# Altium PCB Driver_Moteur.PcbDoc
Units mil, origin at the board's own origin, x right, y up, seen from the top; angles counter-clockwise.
Board outline 3370 x 2000 mil, 2 copper layers (Top Layer, Bottom Layer); 25 components, 15 nets, 72 pads, 0 vias.
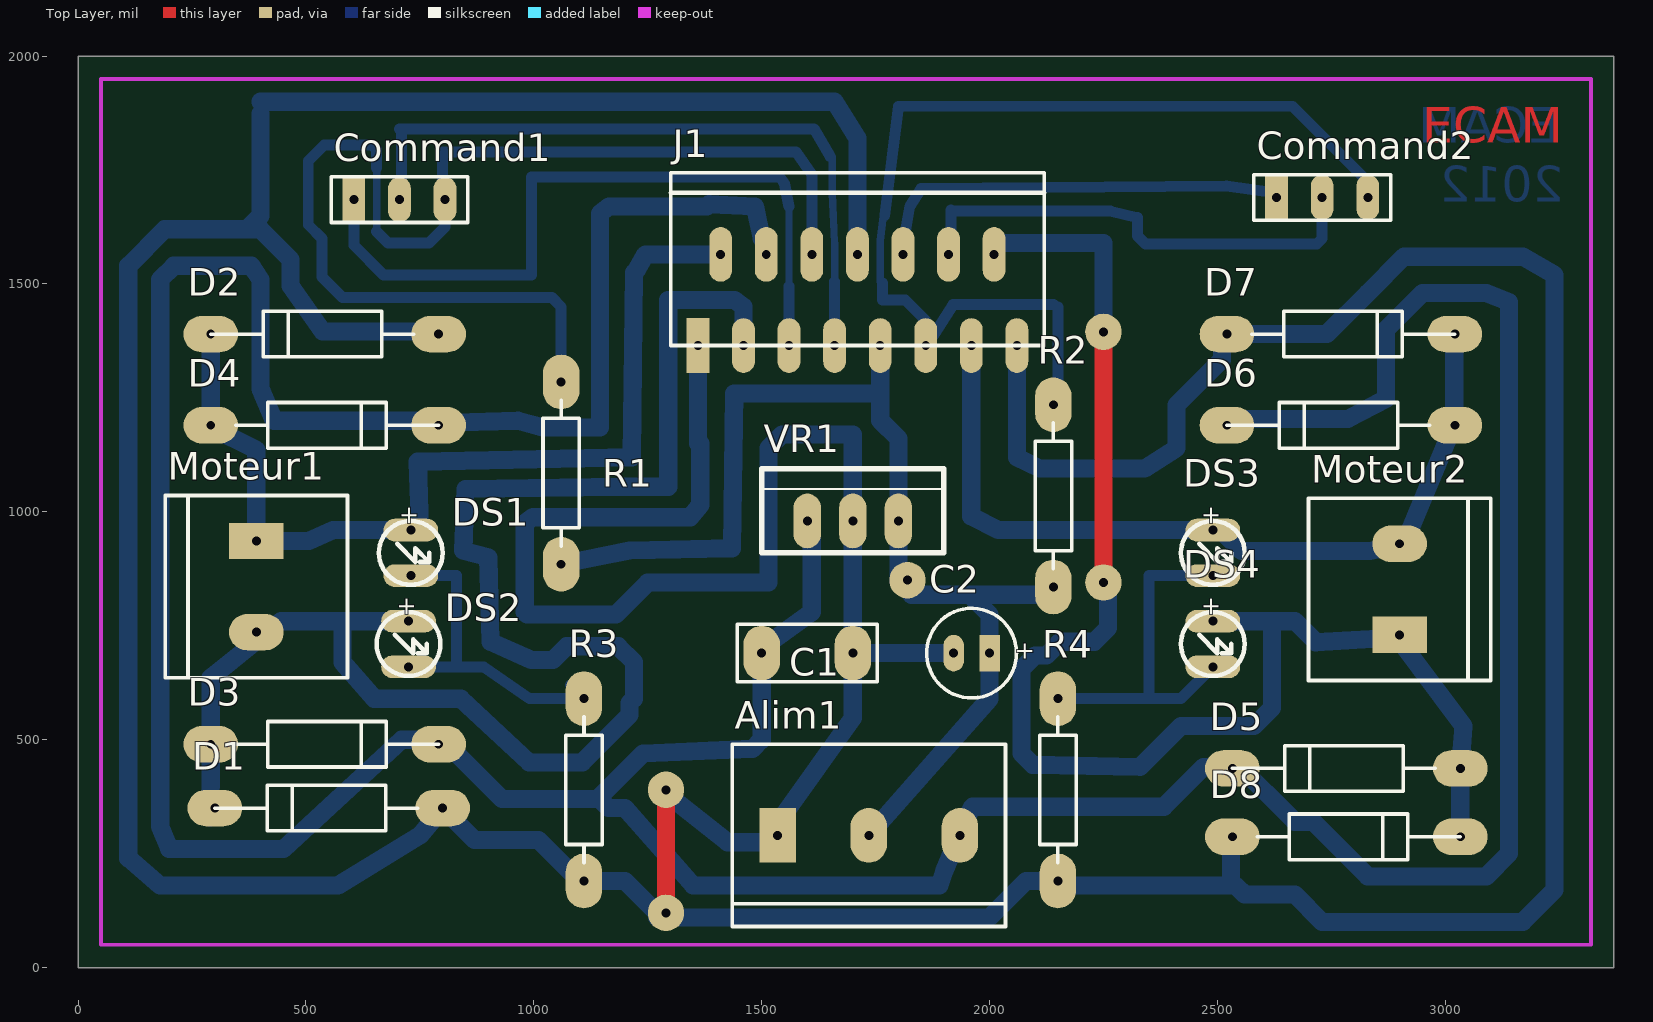
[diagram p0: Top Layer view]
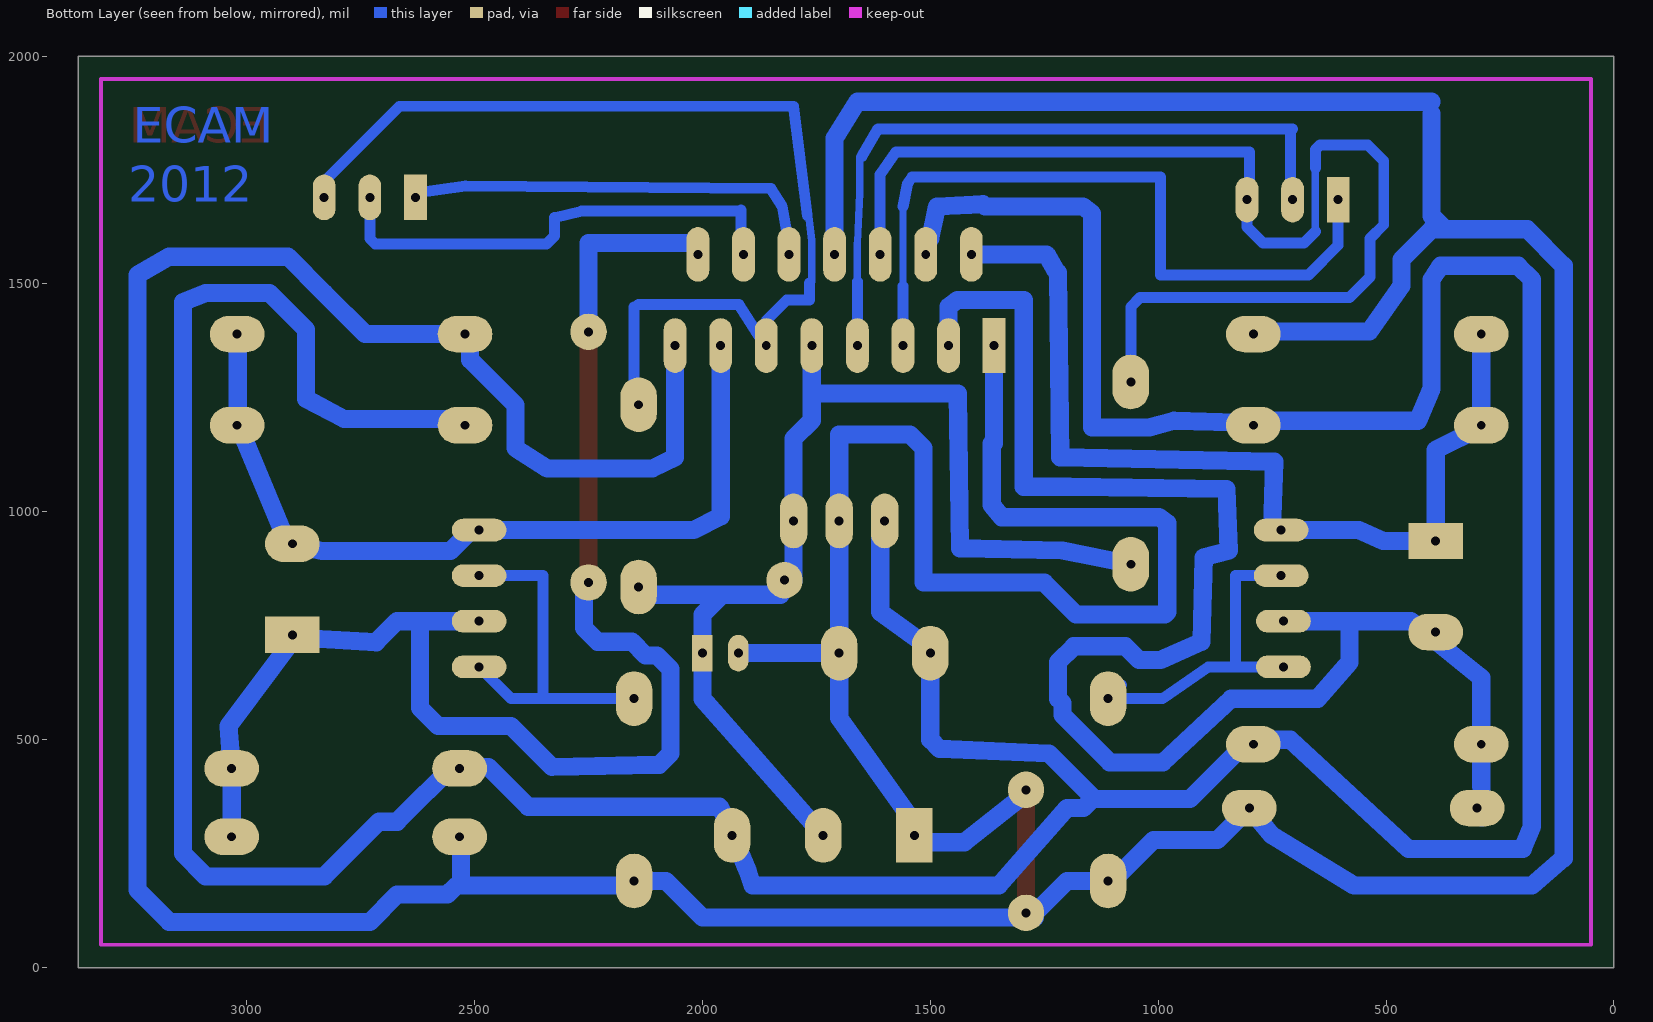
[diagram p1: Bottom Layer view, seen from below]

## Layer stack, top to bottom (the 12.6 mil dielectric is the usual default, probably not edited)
Top Layer: signal copper 1.4
Dielectric: core 12.6, FR-4, Dk 4.8
Bottom Layer: signal copper 1.4

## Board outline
0,0 3370,0 3370,2000 0,2000

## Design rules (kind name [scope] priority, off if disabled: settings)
Clearance "Clearance P DIP" [(IsTrack) vs (IsPad AND(
HasFootprint('DIP*')))] p1: gap=12
Clearance "Clearance PT" [(isTrack) vs (isPad)] p2: gap=16
Clearance "Clearance TT" [(isTrack) vs (isTrack)] p3: gap=24
Clearance "Clearance PP" [(IsPad) vs (IsPad)] p4: gap=24
Clearance [All] p5: gap=40
ComponentClearance [All] p1: gap=10 collisioncheckmode=0
HoleSize [All] p1: absolutevalues=TRUE maxlimit=21.65 minlimit=17.72 maxpercent=80.000 minpercent=20.000
PolygonConnect [All] p1: connectstyle=Relief reliefconductorwidth=10 reliefentries=4 polygonreliefangle="90 Angle"
RoutingCorners [All] p1: cornerstyle=45-Degree minsetback=100 maxsetback=1000
RoutingLayers [All] p1: top layer_v5=FALSE bottom layer_v5=TRUE
RoutingVias "ECAM Vias" [All] p1: holewidth=19.68 width=80 viastyle="Through Hole" minholewidth=17.72 minwidth=60 maxholewidth=21.65 maxwidth=120
SolderMaskExpansion [All] p1: expansion=4
TestPointUsage [All] p1: valid=0 allowmultiple=FALSE
Testpoint [All] p1: side=15 testpointundercomponent=TRUE minsize=40 maxsize=100 preferedsize=60 minholesize=0 maxholesize=40 preferedholesize=32 testpointgrid=1 style=1023 order=0-112345678
Width Width_GND [InNet('GND')] p1: maxlimit=1000 minlimit=24 preferedwidth=40
Width Width_VCC [InNet('VCC')] p2: maxlimit=1000 minlimit=24 preferedwidth=40
Width [All] p3: maxlimit=1000 minlimit=16 preferedwidth=24 bottomlayer_prefwidth=16 minimp=50.000000 maximp=50.000000 favimp=50.000000
14 further rules are at their usual default settings.

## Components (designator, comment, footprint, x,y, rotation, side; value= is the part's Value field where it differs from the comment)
Alim1 "Connecteur 3" CONVIS-3 1535,290 r0 top
C1 "Condensateur" CAPR5.08-7.8x3.2 1500,690 r0 top
C2 "Cond pol radial" CAPPR2-5x6.8 2000,690 r180 top
Command1 "Connecteur 3" HDR1X3 605,1685 r0 top
Command2 "Connecteur 3" HDR1X3 2630,1690 r0 top
D1 "Diode Schottky" DIODE-0.4 800,350 r180 top
D2 "Diode Schottky" DIODE-0.4 791,1390 r180 top
D3 "Diode Schottky" DIODE-0.4 291,490 r0 top
D4 "Diode Schottky" DIODE-0.4 291,1190 r0 top
D5 "Diode Schottky" DIODE-0.4 3033,437 r180 top
D6 "Diode Schottky" DIODE-0.4 3021,1190 r180 top
D7 "Diode Schottky" DIODE-0.4 2521,1390 r0 top
D8 "Diode Schottky" DIODE-0.4 2533,287 r0 top
DS1 "LED" "Led 0.1" 730,960 r270 top
DS2 "LED" "Led 0.1" 725,760 r270 top
DS3 "LED" "Led 0.1" 2490,960 r270 top
DS4 "LED" "Led 0.1" 2490,760 r270 top
J1 "L298" MultiWatt15 1200,1365 r0 top
Moteur1 "Connecteur 2" CONVIS-2 391,936 r270 top
Moteur2 "Connecteur 2" CONVIS-2 2900,730 r90 top
R1 "Résistance" AXIAL-0.4 1060,885 r90 top
R2 "Résistance" AXIAL-0.4 2140,1235 r270 top
R3 "Résistance" AXIAL-0.4 1110,190 r90 top
R4 "Résistance" AXIAL-0.4 2150,190 r90 top
VR1 "7805" "TO-220 V" 1600,980 r0 top

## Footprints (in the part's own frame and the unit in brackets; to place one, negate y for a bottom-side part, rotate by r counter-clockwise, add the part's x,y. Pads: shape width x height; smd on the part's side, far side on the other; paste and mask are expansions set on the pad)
AXIAL-0.4 [mil] "Resistor; 2 Leads"
  oval 120x80 hole 19.68 paste+0 mask+0: 1(0,0) 2(400,0)
  silkscreen extent 40,-40 360,40
CAPPR2-5x6.8 [mil] "Capacitor, Electrolytic, Radial; Body 5 x 6.8 mm (Dia.xH typ); Pin Spacing 2 mm (typ)"
  rect 45x80 hole 19.68 paste+0 mask+0: 1(0,0)
  oval 45x80 hole 19.68 paste+0 mask+0: 2(78.74,0)
  silkscreen extent -59,-98 138,98
CAPR5.08-7.8x3.2 [mil] "Capacitor, Ceramic, Thru-Hole, Dipped Radial; Body 7.8 x 3.2 mm (WxT) Pin Spacing 5.08 mm (typ)"
  oval 80x120 hole 19.68 paste+0 mask+0: 1(0,0) 2(200,0)
  silkscreen extent -54,-63 254,63
CONVIS-2 [mil] "Connecteur à vis 2 contacts Pitch 5.08"
  rect 80x120 hole 19.68 paste+0 mask+0: 1(0,0)
  oval 80x120 hole 19.68 paste+0 mask+0: 2(200,0)
  silkscreen extent -100,-200 300,200
CONVIS-3 [mil] "Connecteur à vis 3 contacts Pitch 5.08"
  rect 80x120 hole 19.68 paste+0 mask+0: 1(0,0)
  oval 80x120 hole 19.68 paste+0 mask+0: 2(200,0) 3(400,0)
  silkscreen extent -100,-200 500,200
DIODE-0.4 [mil] "Tunnel Diode - Dependent Source Model; 2 Leads"
  oval 120x80 hole 19.68 paste+0 mask+0: 1(0,0) 2(500,0)
  silkscreen extent 55,-50 500,50
HDR1X3 [mm] "Connector; Header; 3 Position"
  rect 1.27x2.54 hole 0.5 paste+0 mask+0: 1(0,0)
  oval 1.27x2.54 hole 0.5 paste+0 mask+0: 2(2.54,0) 3(5.08,0)
  silkscreen extent -1.27,-1.27 6.35,1.27
"Led 0.1" [mil] "Led Verticale"
  oval 50x120 hole 19.68 paste+0 mask+0: 1(0,0) 2(100,0)
  silkscreen extent -20,-70 120,70
MultiWatt15 [mil] "MultiWatt15; 15 Leads; Row Spacing 5.08 mm; Pitch 2.54 mm"
  rect 50x120 hole 19.68 paste+0 mask+0: CSA(160,0)
  oval 50x120 hole 19.68 paste+0 mask+0: CSB(860,0) ENA(410,200) ENB(660,0) GND(510,200) input1(360,0) input2(460,0) input3(610,200) input4(710,200) OUT1(210,200) OUT2(260,0) OUT3(760,0) OUT4(810,200) VS(310,200) VSS(560,0)
  silkscreen extent 100,0 920,379
"TO-220 V" [mil] "TO-220 Vertical"
  oval 60x120 hole 19.68 paste+0 mask+0: 1(0,0) 2(100,0) 3(200,0)
  silkscreen extent -100,-70 300,115

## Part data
Alim1 Command1 Command2 J1 Moteur1 Moteur2: "Connecteur"
C2: "Condensateur polatisé"
R1 R2 R3 R4: "Résistance standard"
VR1: "Régulateur 5V"

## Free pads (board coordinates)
  round 80 hole 19.68: 0(2250,845) 1(1290,390) 1(1820,850) 1(2250,1395) 2(1290,120)

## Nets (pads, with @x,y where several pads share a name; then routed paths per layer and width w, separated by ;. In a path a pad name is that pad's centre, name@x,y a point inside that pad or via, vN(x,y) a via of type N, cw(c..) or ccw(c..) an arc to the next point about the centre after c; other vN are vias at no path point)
+5: Alim1.2 C2.1 J1.VSS pad.1@1820,850 R1.1 R2.2 VR1.3 | length 2602.8
  Bottom Layer w24: 1590,1260 1600,1260 ; pad.1@1800,847 pad.1@1829,818 ; R2.2@2133,818 R2.2@2150,835
  Bottom Layer w40: R1.1 1210,915 1435,920 1440,1260 1595,1260 1590,1260 ; 1600,1260 1740,1260 ; Alim1.2 2000,590 2000,775 1957,818 ; J1.VSS@1760,1390 1760,1201 1800,1161 pad.1@1800,847 ; pad.1@1829,818 1957,818 ; R2.2@2133,818 1957,818
E1-2: Command1.3 J1.ENA R1.2 | length 2695.9
  Bottom Layer w16: 655,1615 655,1755
  Bottom Layer w24: 655,1615 680,1590 770,1590 805,1625 Command1.3 800,1690 800,1790 1575,1790 1610,1740 J1.ENA@1610,1590 ; 655,1755 655,1795 645,1805 540,1805 505,1770 505,1630 535,1600 535,1515 580,1470 1040,1470 1060,1450 R1.2@1060,1250
E3-4: Command2.3 J1.ENB R2.1 | length 2555.5
  Bottom Layer w16: 1760,1505 1760,1595 1785,1800 1770,1650
  Bottom Layer w24: 1765,1502 1765,1465 1815,1465 1860,1420 J1.ENB ; 1770,1650 1800,1890 2665,1890 Command2.3@2830,1725 ; J1.ENB@1860,1360 1862.26,1363.57 1920,1455 2140,1455 ; R2.1@2150,1220 2150,1450
GND: Alim1.1 C1.2 C2.2 D1.1 D2.1 D7.1 D8.1 J1.CSA J1.CSB J1.GND pad.1@1290,390 pad.2 R3.1 R4.1 VR1.2 | length 14286.8
  Top Layer w40: pad.2@1290,110 pad.1@1290,390
  Bottom Layer w40: 380,1630 400,1650 400,1874 ; 400,1900 1660,1900 1710,1820 J1.GND@1710,1615 ; D2.1@801,1396 536,1396 466,1496 466,1554 400,1620 190,1620 110,1540 110,240 180,180 570,180 750,290 D1.1 870,280 1010,280 1100,190 1200,190 pad.2@1270,120 ; 980,780 980,975.71 ; 980.36,779.64 985,775 1180,775 1250,845 1515,845 1515,1140 1545,1170 1700,1170 1700,548 Alim1.1@1545,330 ; 980.36,975.36 998.33,988.33 1343.33,988.33 1365,1015 1365,1150 ; pad.2@1270,110 2000,110 2080,190 R4.1 ; pad.1@1280,390 1425,275 Alim1.1@1535,275 ; 1360,1150 J1.CSA@1360,1390 ; C1.2 C2.2 ; J1.CSB@2064,1394 J1.CSB 2060,1120 2110,1095 2340,1095 2410,1140 2410,1234 2510,1334 D7.1@2510,1400 ; R4.1@2150,180 2540,180 2560,160 2670,160 2730,100 3170,100 3240,170 3240,1520 3170,1560 3070,1560 2910,1560 2830,1480 2740,1390 D7.1@2510,1390 ; 2530,190 D8.1@2530,280
I1: Command1.1 J1.input1 | length 1645.9
  Bottom Layer w16: 1560,1495 1560,1670
  Bottom Layer w24: Command1.1@605,1680 605,1585 670,1520 995,1520 995,1735 1540,1735 1550,1720 1560,1670 ; J1.input1 1560,1495
I2: Command1.2 J1.input2 | length 1551.6
  Bottom Layer w16: 1655,1780 1655,1700 1660,1590 1660,1505
  Bottom Layer w24: Command1.2 710,1690 710,1840 ; 705,1840 1615,1840 1650,1780 ; J1.input2 1660,1505
I3: Command2.1 J1.input3 | length 919.9
  Bottom Layer w24: J1.input3@1810,1590 1811,1591 1825,1670 1850,1710 2520,1715 2630,1700 Command2.1
I4: Command2.2 J1.input4 | length 1076
  Bottom Layer w24: J1.input4@1915,1545 1915,1662 ; 1915,1660 2265,1660 2324.38,1645.62 2324.38,1605.62 2342,1588 2718,1588 2730,1600 Command2.2
M1: D2.2 D4.1 DS1.1 J1.OUT1 Moteur1.1 | length 2101.4
  Bottom Layer w40: D2.2@291,1386 291,1186 391,1136 Moteur1.1 506,936 560,960 750,960 745,1110 1215,1120 1220,1525 ; 1225,1530 1245,1565 J1.OUT1@1405,1565
M2: D1.2 D3.1 DS2.1 J1.OUT2 Moteur1.2 | length 3619
  Bottom Layer w40: D1.2@290,330 290.19,350.09 291,436 291,636 400.52,724.18 445,760 DS2.1@740,760 ; Moteur1.2 Moteur1.2@391,744 ; 580,760 580,670 650,590 840,590 990,450 1106,450 1210,554 1210,580 1220,590 1220,670 1185,705 1072,705 1042,675 995,675 905,715 900,900 845,915 850,1050 1195,1055 1295,1055 1295,1440 1295,1465 1440,1465 1460,1450 J1.OUT2
M3: D6.1 D7.2 DS3.1 J1.OUT3 Moteur2.2 | length 1832.4
  Bottom Layer w40: J1.OUT3@1960,1380 1960,1170 1960,990 2020,960 DS3.1 ; DS3.1@2507.37,960 2553.37,914 2835,914 2910,930 3020,1195 D7.2@3020,1390
M4: D5.1 D8.2 DS4.1 J1.OUT4 Moteur2.1 pad.0 pad.1@2250,1395 | length 3214.3
  Top Layer w40: pad.0 pad.1@2250,1395
  Bottom Layer w40: J1.OUT4@2010,1590 2250,1590 pad.1@2250,1395 ; 2090,450 2070,470 2070,655 2100,685 2125,685 2155,715 2230,715 2260,745 pad.0@2260,855 ; 2095,445 2330,440 2420,530 2580,530 2620,570 2620,760 ; DS4.1 2670,760 2716,714 2895,724 3040,530 D5.1 D8.2
NetDS1_2: DS1.2 DS2.2 R3.2 | length 694.5
  Bottom Layer w24: DS2.2@750,660 890,660 990,590 R3.2 R3.2@1080,620 ; DS1.2@760,860 830,860 830,660
NetDS3_2: DS3.2 DS4.2 R4.2 | length 779
  Bottom Layer w24: R4.2 2420,590 DS4.2 ; 2350,590 2350,860 DS3.2
VIN: Alim1.3 C1.1 D3.2 D4.2 D5.2 D6.2 J1.VS VR1.1 | length 9888.2
  Bottom Layer w24: 1140,1185 1145,1185
  Bottom Layer w40: 200,260 180,310 180,1510 210,1540 380,1540 400,1510 400,1270 430,1200 D4.2@791,1200 ; 210,260 450,260 710,500 800,500 930,370 1140,370 1220,450 1240,470 1480,480 1500,500 C1.1@1500,700 ; D4.2@790,1195 965,1200 1020,1185 1145,1185 1145,1655 1165,1670 1380,1670 ; 1142.12,372.12 1164.24,350 1200,350 1350,180 1890,180 1900,210 Alim1.3@1935,295 ; 1385,1675 1485,1670 J1.VS@1500,1600 ; C1.1@1490,700 C1.1@1500,700 ; VR1.1@1610,1010 1610,780 C1.1@1500,700 ; Alim1.3@1925,285 1963,353 2383,353 2470,440 D5.2@2540,440 ; D6.2@2521,1204 2786,1204 2870,1248 2870,1400 2950,1480 3090,1480 3140,1460 3140,250 3090,200 2830,200 2710,320 2670,320 D5.2@2540,450

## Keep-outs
Keep-Out Layer:
  lines w8: 50,50 50,175 50,1950 3320,1950 3320,50 375,50 50,50

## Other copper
Top Layer:
  text "ECAM" at 2950,1810 h78.74
  text ".GTL" at 6764,-2628 h90
Bottom Layer:
  text "ECAM" at 3250,1810 h78.74
  text "2012" at 3260,1680 h78.74
  text ".GBL" at 6764,-2628 h90
Multi-Layer:

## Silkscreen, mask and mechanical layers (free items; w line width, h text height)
Top Overlay:
  text ".GTO" at 6764,-2628 h90
Top Paste:
  text ".GTP" at 6764,-2628 h90
Bottom Paste:
  text ".GBP" at 6764,-2628 h90
Top Solder:
  text ".GTS" at 6764,-2628 h90
Bottom Solder:
  text ".GBS" at 6764,-2628 h90
Mechanical 1:
  the board outline again, w7.87
Mechanical 16:
  circle w3.94: c5670,-2615 r55.12
  lines w5: -3175,-1325 -2975,-1325 ; -3175,575 -2975,575 ; -3175,2475 -2975,2475 ; -695,-3225 -695,-3025 ; -695,4175 -695,4375 ; 2180,-3225 2180,-3025 ; 2180,4175 2180,4375 ; 2815,-2725 7315,-2725 ; 2815,-2425 7315,-2425 ; 2815,-2125 4315,-2125 ; 4315,-3025 4315,-2425 4315,-1825 ; 5055,-3225 5055,-3025 ; 5055,4175 5055,4375 ; 6415,-3025 6415,-2425 ; 7315,2465 7515,2465 ; 2815,-3025 1415,-3025 1415,-1825 2815,-1825 ; 2815,-3025 7315,-3025 ; 2815,-3025 2815,-1825 ; 2815,-1825 4315,-1825 ; 4315,-1825 7315,-1825 7315,-3025 ; 7315,-3025 7315,4175 -2975,4175 -2975,-3025 7315,-3025 ; -3175,-3225 -3175,4375 7515,4375 7515,-3225 -3175,-3225
  text "1" at -2143,4240 h70
  text "2" at 717,4240 h70
  text "3" at 3597,4240 h70
  text "4" at 6467,4240 h70
  text "A" at -3100,3334 h70
  text "A" at 7390,3324 h70
  text "B" at -3100,1442 h70
  text "C" at -3100,-468 h70
  text "Concepteur du circuit :" at 2865,-1925 h45
  text "TITRE :" at 4365,-1925 h45
  text "Votre Nom" at 3240,-2075 h80
  text "Le nom du circuit" at 4625,-2195 h100
  text "Concepteur du PCB :" at 2865,-2220 h45
  text "ECAM" at 1650,-2235 h240
  text "D" at -3100,-2358 h70
  text "D" at 7390,-2368 h70
  text "Votre Nom" at 3235,-2380 h80
  text "Rue du TIR, 14" at 1720,-2505 h60
  text "Date :" at 2865,-2525 h45
  text "PART NO.:" at 4365,-2525 h45
  text "Layer :" at 6465,-2525 h45
  text ".Print_Date" at 3255,-2560 h70
  text "1" at 4370,-2645 h60
  text "C" at 5645,-2645 h60
  text "ECAM" at 5751,-2660 h100
  text ".Print_Time" at 3260,-2690 h70
  text "1060 Bruxelles" at 1720,-2725 h60
  text "Nom du fichier :" at 2865,-2825 h45
  text "DWG NO:" at 4365,-2825 h45
  text ".Print_Scale" at 6625,-2905 h40
  text ".Printout_Name" at 4515,-2940 h60
  text ".Pcb_File_Name_No_Path" at 2915,-2945 h70
  text "1" at -2143,-3160 h70
  text "2" at 717,-3160 h70
  text "3" at 3597,-3160 h70
  text "4" at 6467,-3160 h70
